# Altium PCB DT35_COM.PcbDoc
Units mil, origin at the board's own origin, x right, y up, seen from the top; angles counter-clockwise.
Board outline 1965 x 1965 mil, 2 copper layers (Top Layer, Bottom Layer); 79 components, 63 nets, 257 pads, 96 vias.
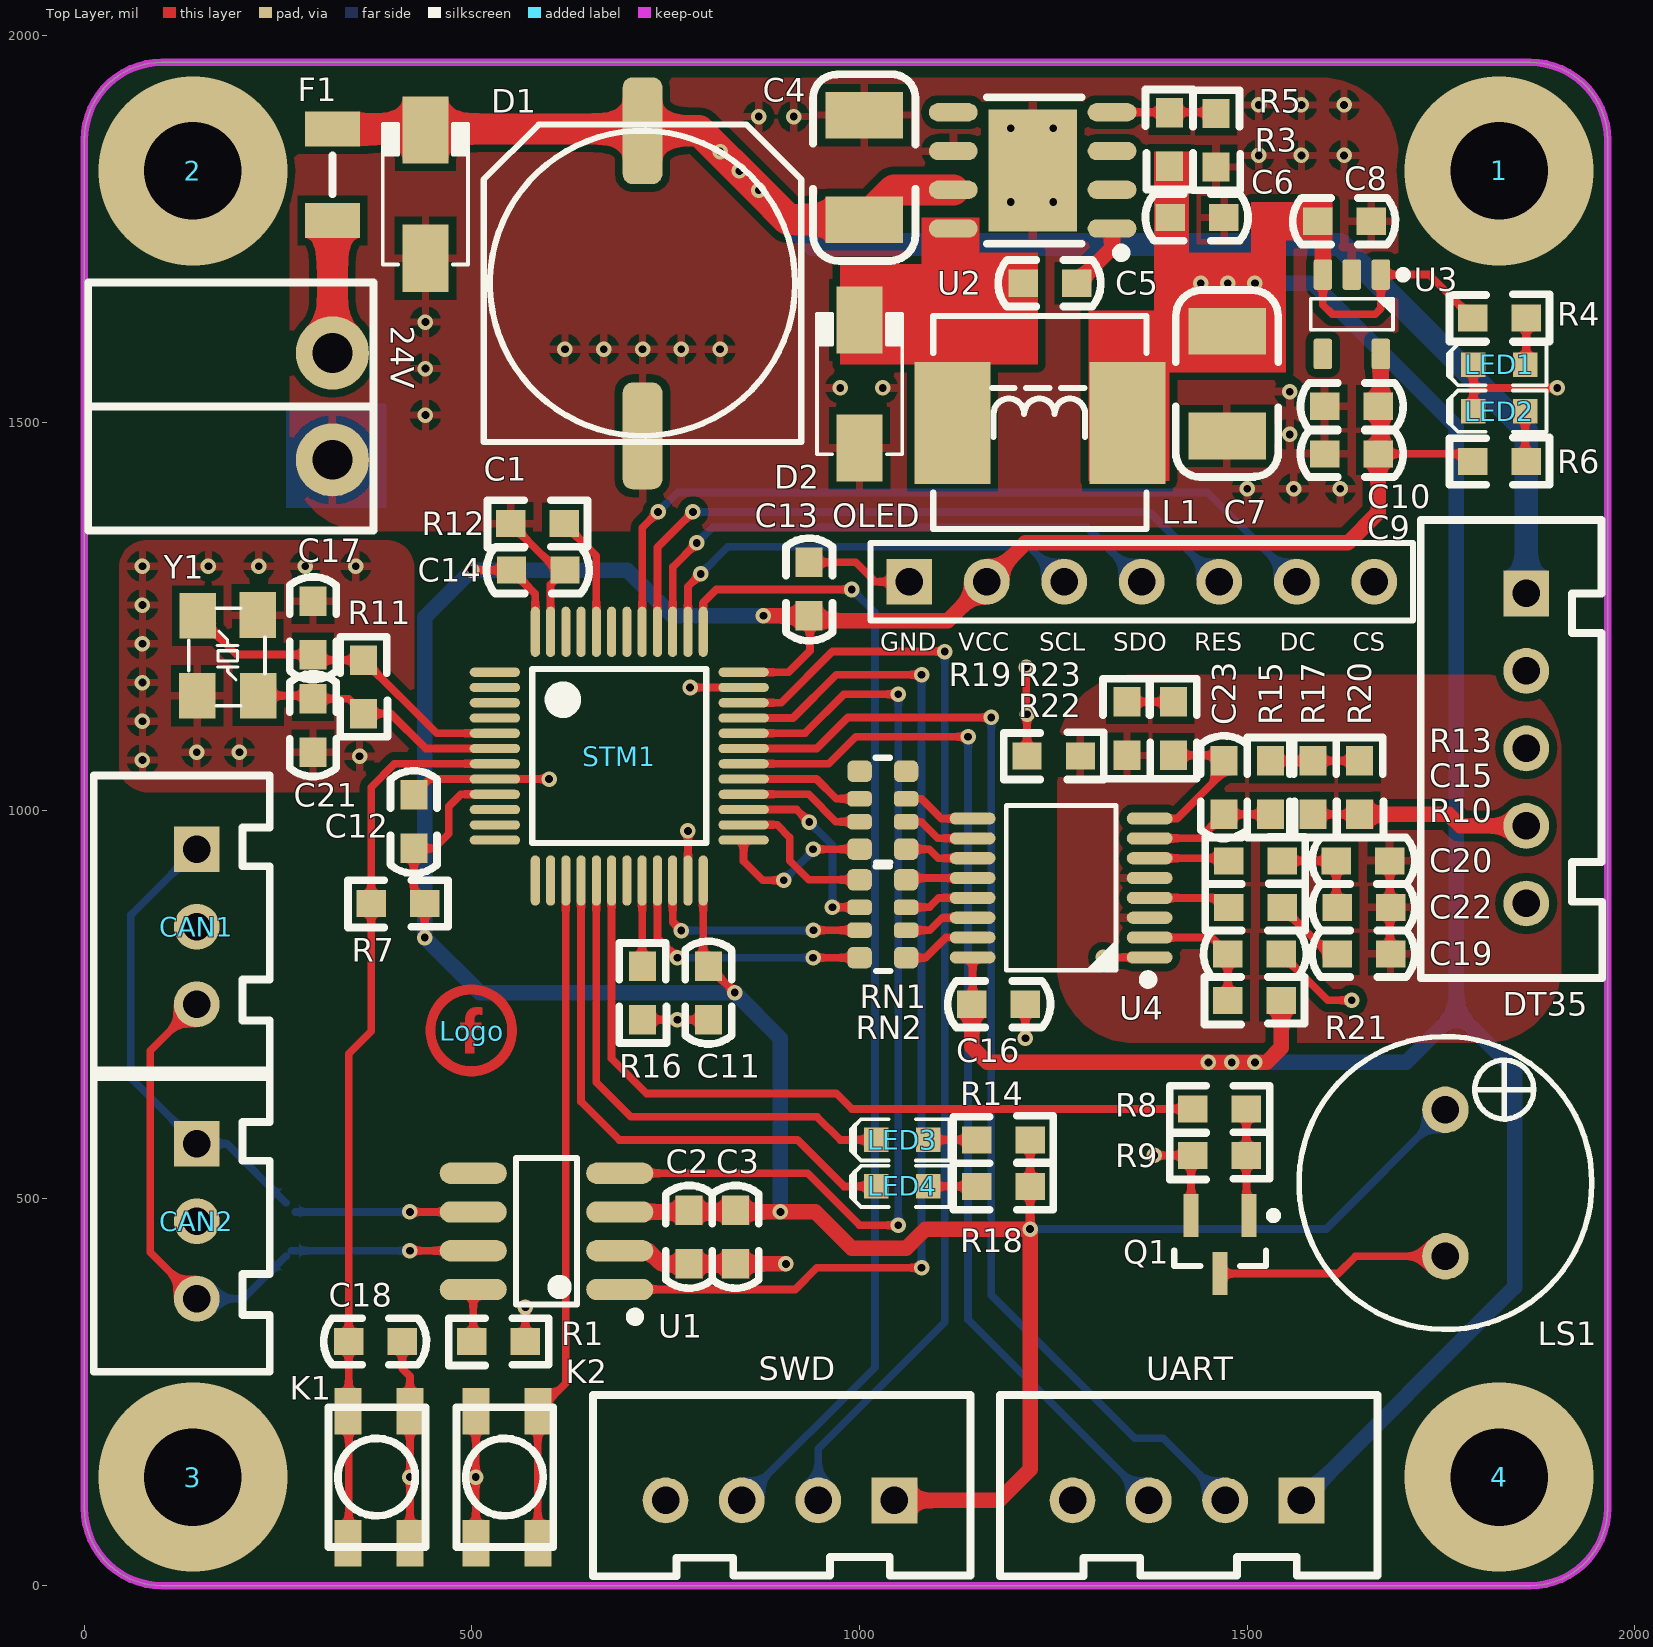
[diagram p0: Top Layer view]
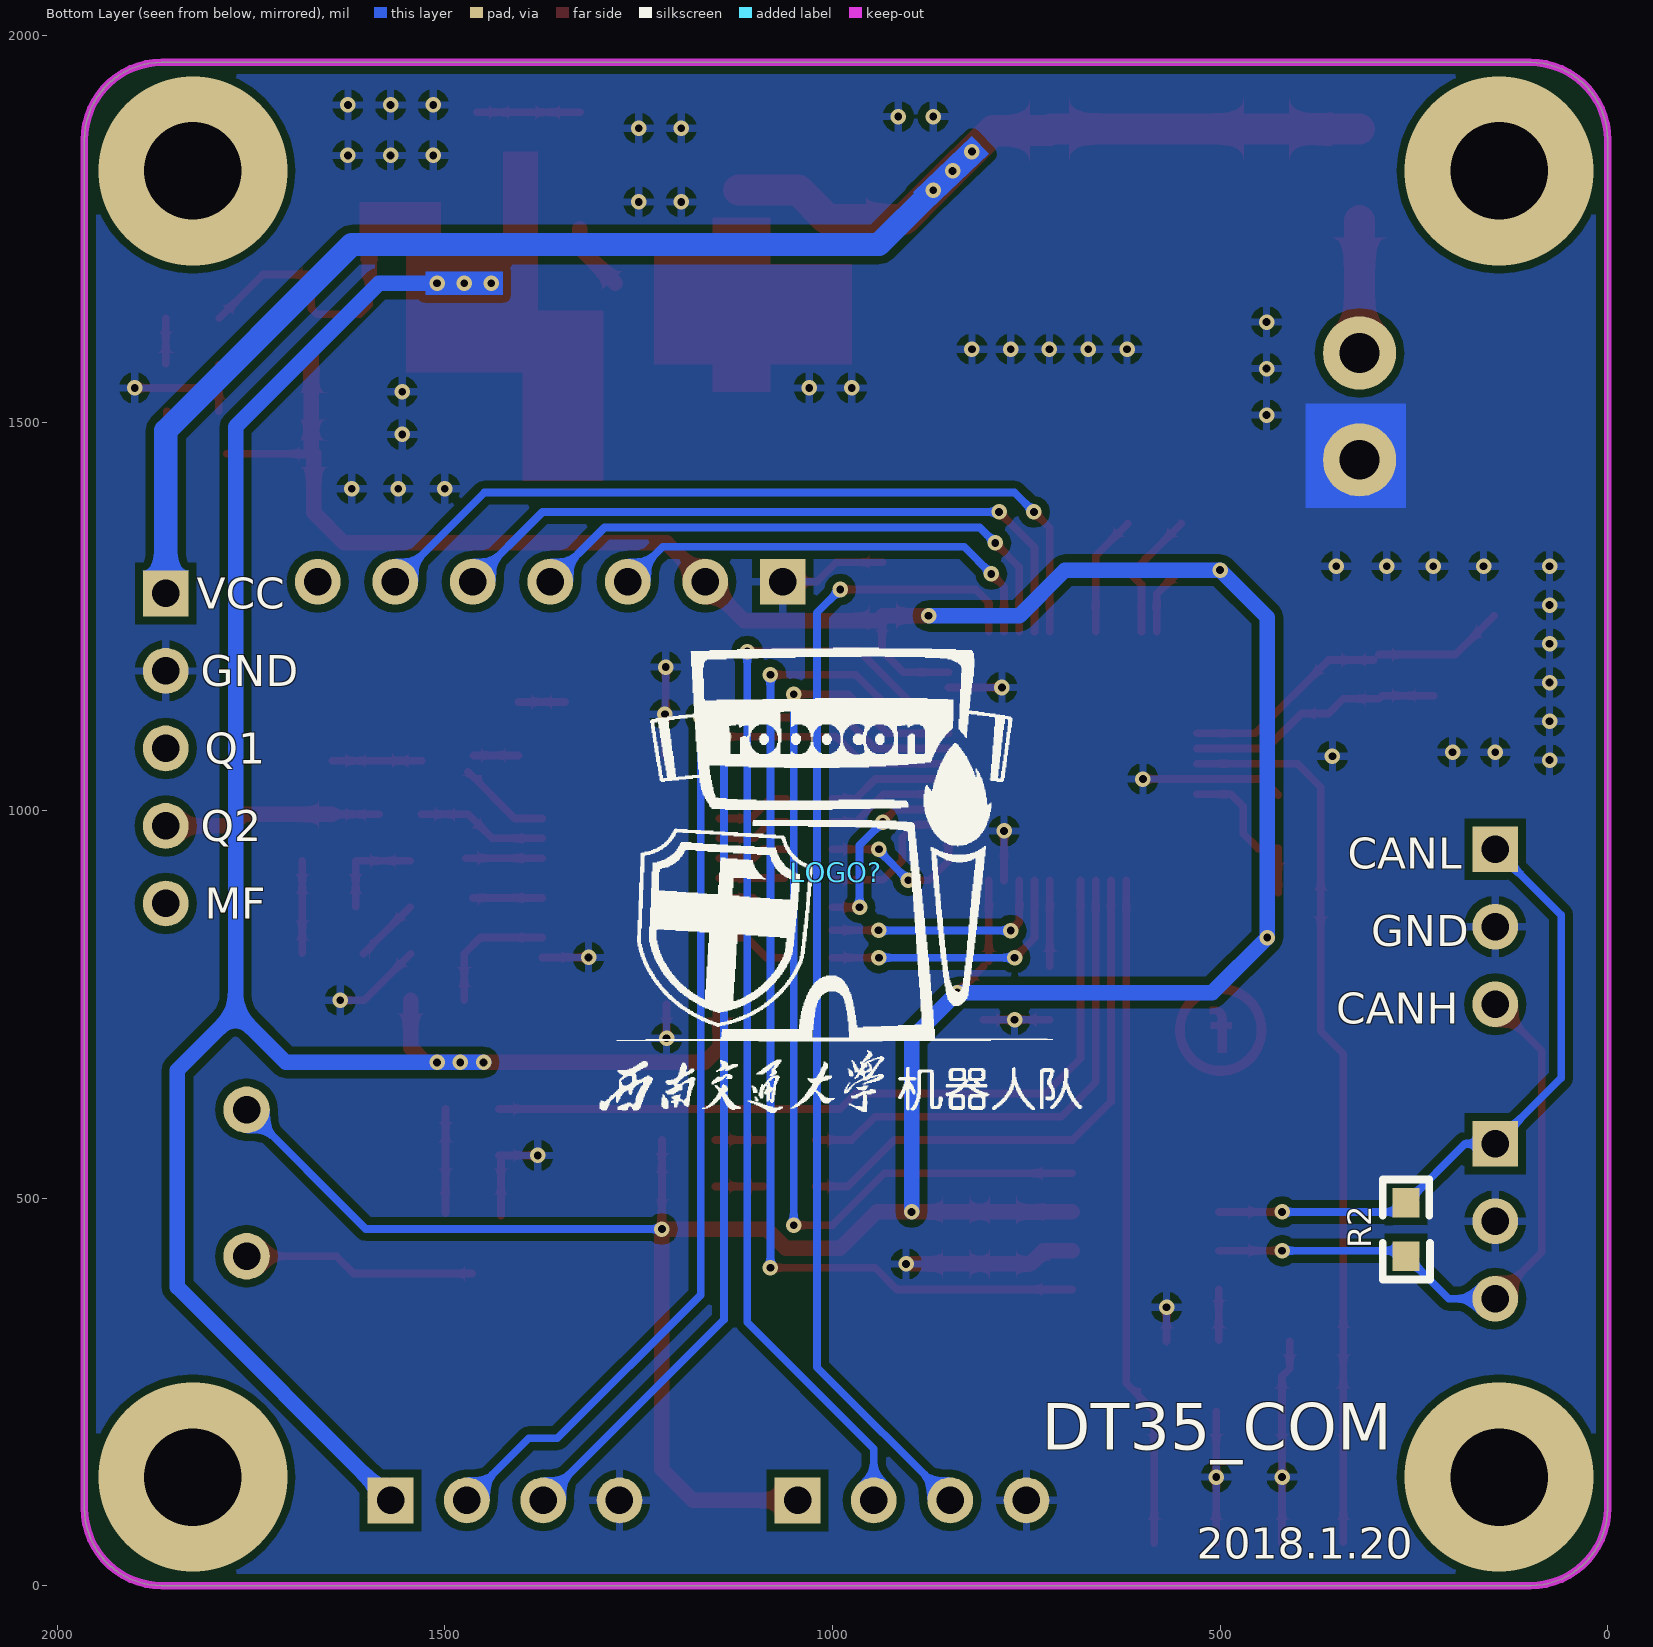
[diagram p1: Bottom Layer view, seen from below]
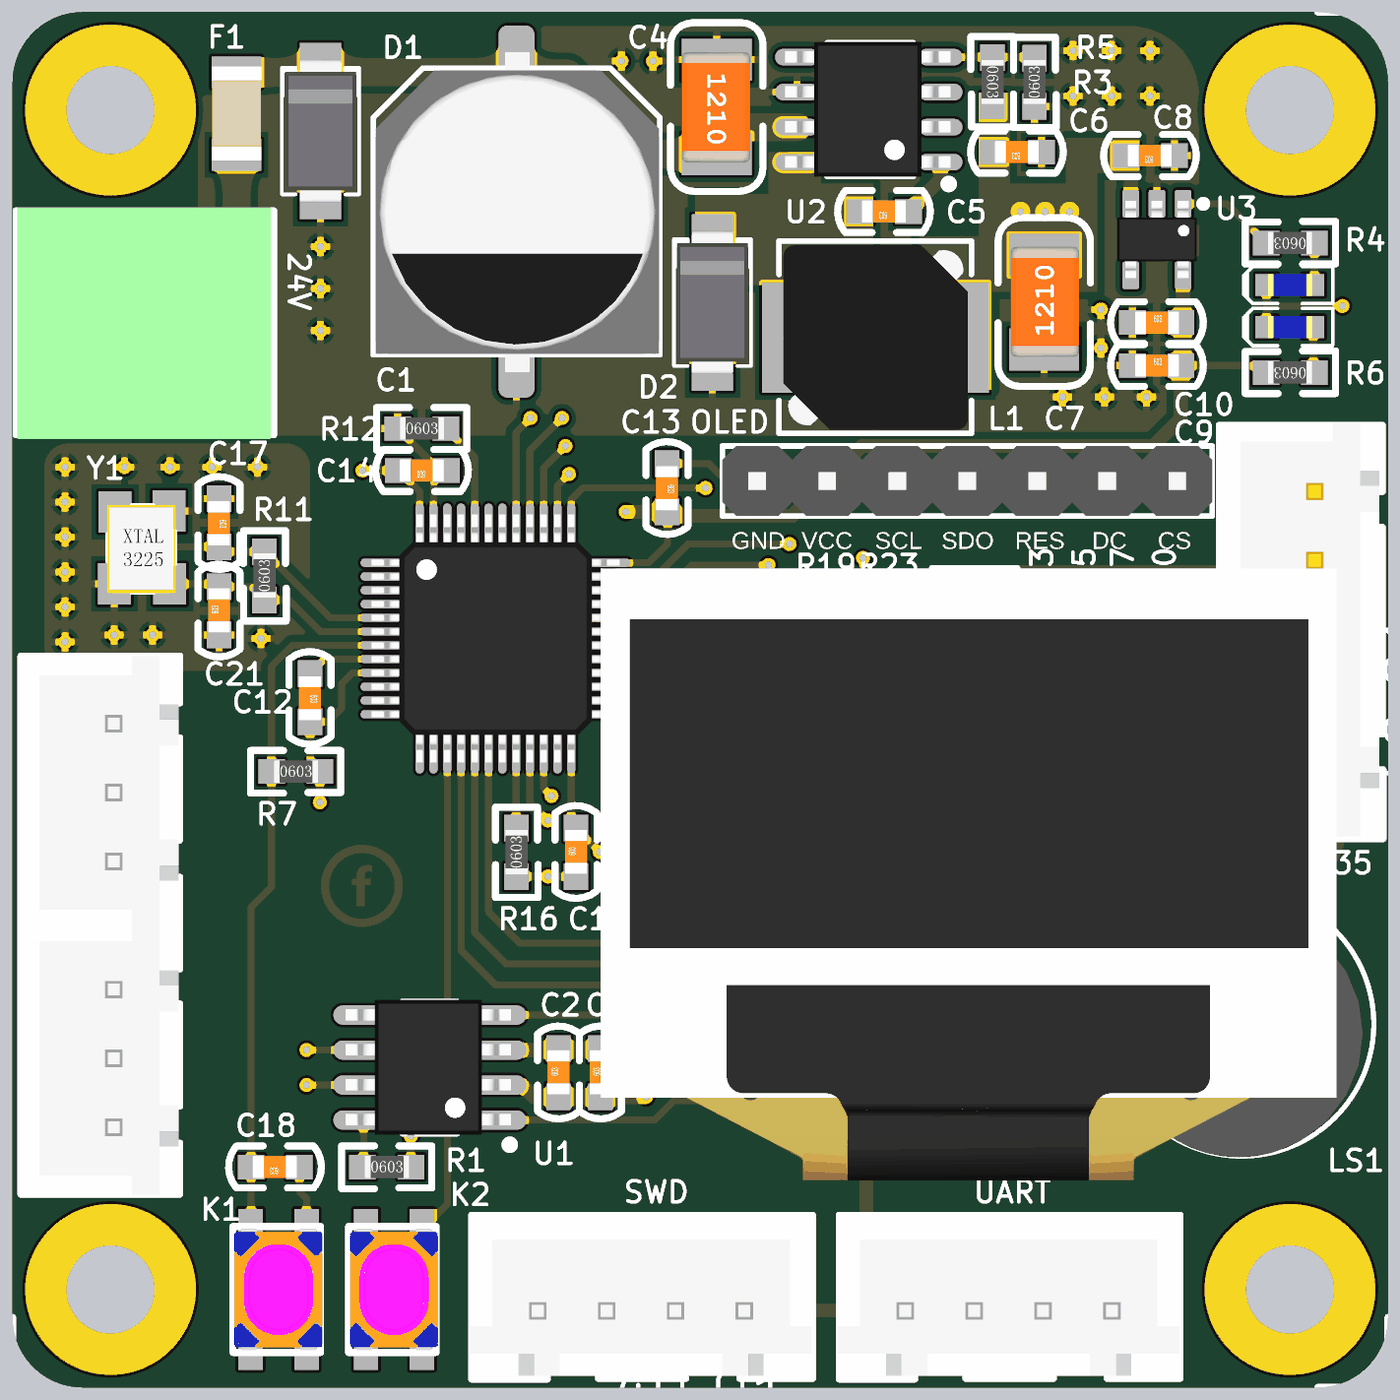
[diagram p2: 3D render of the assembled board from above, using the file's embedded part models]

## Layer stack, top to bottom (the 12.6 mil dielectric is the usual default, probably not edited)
Top Solder: solder mask 0.4, Solder Resist, Dk 3.5
Top Layer: signal copper 1.4
Dielectric 1: dielectric 12.6, FR-4, Dk 4.8
Bottom Layer: signal copper 1.4
Bottom Solder: solder mask 0.4, Solder Resist, Dk 3.5

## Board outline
100,0 cw(c100,100) 0,100 0,1865 cw(c100,1865) 100,1965 1865,1965 cw(c1865,1865) 1965,1865 1965,100 cw(c1865,100) 1865,0

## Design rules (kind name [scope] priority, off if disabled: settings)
Clearance [All] p1: gap=6 except(10: Arc-Poly Track-Poly SMDPad-Poly THPad-Poly Via-Poly Fill-Poly Poly-Poly Poly-Region Poly-Text)
HoleSize [All] p1: absolutevalues=TRUE maxlimit=1000 minlimit=1 maxpercent=80.000 minpercent=20.000
MinimumSolderMaskSliver [All] p1: minsoldermaskwidth=0
PolygonConnect [All] p1: connectstyle=Relief reliefconductorwidth=10 reliefentries=4 polygonreliefangle="90 Angle" airgapwidth=10
RoutingVias [All] p1: holewidth=28 width=50 viastyle="Through Hole" minholewidth=10 minwidth=20 maxholewidth=100 maxwidth=100
SilkToSilkClearance [All] p1: silktosilkclearance=0
SilkToSolderMaskClearance [IsPad] p1: minsilkscreentomaskgap=0 clearancetoexposedcopper=TRUE
SolderMaskExpansion [All] p1: expansion=4
Width [All] p1: maxlimit=1000 minlimit=10 preferedwidth=10
26 further rules are at their usual default settings.

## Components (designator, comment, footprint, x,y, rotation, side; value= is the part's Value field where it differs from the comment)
1 "Hole" HOLE2 1825,1825 r90 top
2 "Hole" HOLE2 140,1825 r90 top
3 "Hole" HOLE2 140,140 r90 top
4 "Hole" HOLE2 1825,140 r90 top
24V "Power" MEM030-350-2P 320,1590 r90 top
C1 "Cap_ELEC" C10X10 720,1680 r270 top
C2 "Cap" C0603 780,415 r90 top
C3 "Cap" C0603 840,415 r90 top
C4 "Cap" C1210 1000,1835 r270 top
C5 "Cap" C0603 1280,1680 r180 top
C6 "Cap" C0603 1470,1765 r180 top
C7 "Cap" C1210 1480,1545 r90 top
C8 "Cap" C0603 1660,1760 r180 top
C9 "Cap" C0603 1600,1460 r0 top
C10 "Cap" C0603 1600,1521.35 r0 top
C11 "Cap" C0603 805,730 r90 top
C12 "Cap" C0603 425,1020 r270 top
C13 "Cap" C0603 935,1320 r270 top
C14 "Cap" C0603 620,1310 r180 top
C15 "Cap" C0603 1475,815 r0 top
C16 "Cap" C0603 1145,750 r0 top
C17 "Cap" C0603 295,1270 r270 top
C18 "Cap" C0603 410,315 r180 top
C19 "Cap" C0603 1685,815 r180 top
C20 "Cap" C0603 1615,935 r0 top
C21 "Cap" C0603 295,1075 r90 top
C22 "Cap" C0603 1685,875 r180 top
C23 "Cap" C0603 1470,995 r90 top
CAN1 "Header 3" XH2.54-3 145,950 r270 top
CAN2 "Header 3" XH2.54-3 145,570 r270 top
D1 "Diode" DO-214AC 440,1795 r90 top
D2 "Diode" DO-214AC 1000,1550 r90 top
DT35 "Header 5" XH2.54-5 1860,1280 r270 top
F1 "Fuse" FUSE_1206 320,1820 r90 top
K1 "SW-PB" SW_4.2x3.2 340,55 r90 top
K2 "SW-PB" SW_4.2x3.2 505,55 r90 top
L1 "100uH" L-SMD-7X7 1120,1500 r0 top
LED1 "LED" LED_0603_BLUE 1825,1575 r180 top
LED2 "LED" LED_0603_BLUE 1825,1515 r180 top
LED3 "LED" LED_0603_BLUE 1055,575 r180 top
LED4 "LED" LED_0603_BLUE 1055,515 r180 top
Logo "Logo" Logo_f_3mm 500,715 r0 top
LOGO? "Robocon" SWJTURobocon_2*2cm 995,920 r180 bottom
LS1 "Buzzer" BUZZER_4.8MM 1755,520 r270 top
OLED "OLED" OLED_0.96_SPI 815,295 r0 top
Q1 "BJT_NPN" SOT23 1465,440 r270 top
R1 "Res" R0603 500,315 r0 top
R2 "Res" R0603 260,425 r90 bottom
R3 "Res" R0603 1400,1900 r270 top
R4 "Res" R0603 1860,1635 r180 top
R5 "Res" R0603 1460,1830 r90 top
R6 "Res" R0603 1860,1450 r180 top
R7 "Res" R0603 370,880 r0 top
R8 "Res" R0603 1430,615 r0 top
R9 "Res" R0603 1430,555 r0 top
R10 "Res" R0603 1545,875 r180 top
R11 "Res" R0603 360,1125 r90 top
R12 "Res" R0603 550,1370 r0 top
R13 "Res" R0603 1545,935 r180 top
R14 "Res" R0603 1220,575 r180 top
R15 "Res" R0603 1530,995 r90 top
R16 "Res" R0603 720,730 r90 top
R17 "Res" R0603 1585,995 r90 top
R18 "Res" R0603 1220,515 r180 top
R19 "Res" R0603 1405,1140 r270 top
R20 "Res" R0603 1645,995 r90 top
R21 "Res" R0603 1475,755 r0 top
R22 "Res" R0603 1285,1070 r180 top
R23 "Res" R0603 1345,1140 r270 top
RN1 "?K" RES-Pack-1*4-0603 1060,810 r180 top
RN2 "?K" RES-Pack-1*4-0603 1060,950 r180 top
STM1 "STM32F103C" STM32F_48 690,1070 r0 top
SWD "J-Link" "4PIN-2.54 A" 1045,110 r180 top
U1 "VP230" SOIC-8-150mil 595,455 r180 top
U2 "TPS5430" TPS5430 1220,1825 r180 top
U3 "XC6219" SOT23-5 1635,1640 r270 top
U4 "ADS868x" TSSOP_16 1260,900 r180 top
UART "UART" "4PIN-2.54 A" 1570,110 r180 top
Y1 "XTAL" XTAL-3225 185,1200 r0 top

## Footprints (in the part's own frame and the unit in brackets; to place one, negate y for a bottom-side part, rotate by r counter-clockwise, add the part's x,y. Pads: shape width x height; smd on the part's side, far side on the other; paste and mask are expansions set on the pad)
"4PIN-2.54 A" [mm]
  rect 1.5x1.5 hole 0.9: 1(0,0)
  round 1.5 hole 0.9: 2(2.5,0) 3(5,0) 4(7.5,0)
  silkscreen extent -2.49,-3.45 9.88,2.49, body extent -2.47,-3.38 9.93,2.37, height 7
BUZZER_4.8MM [mil]
  round 60 hole 35.43: 1(-93.86,0.75) 2(95.12,0.75)
  silkscreen extent -188,-188 190,190, body extent -163,-180 191,174, height 177
C10X10 [mm]
  rrect50% 3.5x1.3 smd: 1(-5,0) 2(5,0)
  silkscreen extent -5.2,-5.2 5.2,5.2, body extent -5.77,-5.12 5.83,5.18, height 10.21
C0603 [mil]
  rect 38x35 smd: 1(0,0) 2(69,0)
  silkscreen extent -31,-30 101,30, body extent 4,-16 67,16, height 12
C1210 [mil]
  rect 60x100 smd: 1(-62,6) 2(73,6)
  silkscreen extent -115,-60 126,72, body extent -73,-44 85,54, height 67
DO-214AC [mm] "JEDEC DO214 variation AC. SMA"
  rect 2.2x1.5 smd: 1(-2.1,0) 2(2.1,0)
  silkscreen extent -2.3,-1.4 2.3,1.4, body extent -2.6,-1.3 2.6,1.3, height 2.42
FUSE_1206 [mm] "Chip Capacitor, Body 3.2x1.6mm, 1206, IPC Medium Density"
  rect 1.15x1.8 smd: 1(-1.5,0) 2(1.5,0)
  silkscreen extent -0.64,0 0.64,0, body extent -1.7,-0.9 1.7,0.9, height 1.74
HOLE2 [mil]
L-SMD-7X7 [mm] "7X7mm的贴片电感"
  rect 2.5x4 smd: 1(0,0) 2(5.73,0)
  silkscreen extent -0.64,-3.48 6.35,3.51, body extent -0.48,-3.35 6.22,3.35, height 2.9
LED_0603_BLUE [mm] "Chip Capacitor, 2-Leads, Body 1.6x0.8mm, IPC Medium Density"
  rect 0.8x0.8 smd: 1(-0.85,0) 2(0.85,0)
  Top Layer pour cut-out: -0.5,0.5 0.5,0.5 0.5,-0.5 -0.5,-0.5
  silkscreen extent -1.55,-0.67 1.68,0.67, body extent -0.8,-0.4 0.8,0.4, height 0.75
Logo_f_3mm [mil]
  Top Layer drawing of 1039 lines, arcs and shapes, not listed
MEM030-350-2P [mm]
  round 2.4 hole 1.3: 1(0,0) 2(-3.5,0)
  silkscreen extent -5.81,-1.35 2.31,8, body extent -5.96,-1.25 2.44,7.95, height 7.25
OLED_0.96_SPI [mm] "0.96寸OLED SPI"
  rect 1.5x1.5 hole 0.9: 1(6.325,25.4)
  round 1.5 hole 0.9: 2(8.865,25.4) 3(11.405,25.4) 4(13.945,25.4) 5(16.485,25.4) 6(19.025,25.4) 7(21.565,25.4)
  silkscreen extent 5.05,24.13 22.83,26.67, body extent 0,0 27.94,27.3, height 8.54
R0603 [mil] "1/10W"
  rect 38x35 smd: 1(0,0) 2(69,0)
  silkscreen extent -30,-31 99,30, body extent 4,-16 66,16, height 18
RES-Pack-1*4-0603 [mm] "4排阻,0603封装"
  rrect50% 0.8x0.7 smd: 1(0,0) 4(0,-2.554) 5(1.522,-2.554) 8(1.522,0)
  rrect50% 0.8x0.5 smd: 2(0,-0.902) 3(0,-1.652) 6(1.522,-1.652) 7(1.522,-0.902)
  silkscreen extent 0.51,-3 1,0.43, body extent 0,-3 1.52,0.43, height 0.38
SOIC-8-150mil [mm]
  oval 2.2x0.7 smd: 1(-2.429,1.853) 2(-2.429,0.583) 3(-2.429,-0.687) 4(-2.429,-1.957) 5(2.371,-1.957) 6(2.371,-0.687) 7(2.371,0.583) 8(2.371,1.853)
  silkscreen extent -3.08,-2.45 0.97,2.9, body extent -2.98,-2.51 3.02,2.39, height 1.75
SOT23 [mm] "SOT23, 3-Leads, Body 3.0x2.5mm (max), Pitch 0.95mm, IPC Medium Density"
  rect 1.4x0.5 smd: 1(-0.95,0.95) 2(-0.95,-0.95) 3(0.95,0)
  silkscreen extent -1.07,-1.5 0.7,1.88, body extent -1.4,-1.45 1.4,1.45, height 1.29
SOT23-5 [mm]
  round 0.5 on Mech14: 0(0,0)
  rrect25% 1x0.6 smd: 1(-1.3,0.95) 2(-1.3,0) 3(-1.3,-0.95) 4(1.3,-0.95) 5(1.3,0.95)
  silkscreen extent -1.42,-1.35 0.51,1.81, body extent -1.4,-1.45 1.4,1.45, height 1.44
STM32F_48 [mm] "TSQFP, 48-Leads, Body 9.0x9.0mm (max), Pitch 0.50mm, IPC Medium Density"
  oval 1.65x0.3 smd: 1(-4.075,2.75) 2(-4.075,2.25) 3(-4.075,1.75) 4(-4.075,1.25) 5(-4.075,0.75) 6(-4.075,0.25) 7(-4.075,-0.25) 8(-4.075,-0.75) 9(-4.075,-1.25) 10(-4.075,-1.75) 11(-4.075,-2.25) 12(-4.075,-2.75) 25(4.075,-2.75) 26(4.075,-2.25) 27(4.075,-1.75) 28(4.075,-1.25) 29(4.075,-0.75) 30(4.075,-0.25) 31(4.075,0.25) 32(4.075,0.75) 33(4.075,1.25) 34(4.075,1.75) 35(4.075,2.25) 36(4.075,2.75)
  oval 0.3x1.65 smd: 13(-2.75,-4.075) 14(-2.25,-4.075) 15(-1.75,-4.075) 16(-1.25,-4.075) 17(-0.75,-4.075) 18(-0.25,-4.075) 19(0.25,-4.075) 20(0.75,-4.075) 21(1.25,-4.075) 22(1.75,-4.075) 23(2.25,-4.075) 24(2.75,-4.075) 37(2.75,4.075) 38(2.25,4.075) 39(1.75,4.075) 40(1.25,4.075) 41(0.75,4.075) 42(0.25,4.075) 43(-0.25,4.075) 44(-0.75,4.075) 45(-1.25,4.075) 46(-1.75,4.075) 47(-2.25,4.075) 48(-2.75,4.075)
  silkscreen extent -2.85,-2.85 2.85,2.85, body extent -4.5,-4.5 4.5,4.5, height 1.59
SW_4.2x3.2 [mil]
  rect 60x35 smd: 1(0,0) 1(170,0) 2(0,-80) 2(170,-80)
  silkscreen extent -5,-100 175,25, body extent -6,-103 176,23, height 98
SWJTURobocon_2*2cm [mil]
  silkscreen extent -305,-310 317,289
TPS5430 [mm]
  oval 1.6x0.6 smd: 1(-2.684,1.889) 2(-2.684,0.619) 3(-2.684,-0.651) 4(-2.684,-1.921) 5(2.516,-1.921) 6(2.516,-0.651) 7(2.516,0.619) 8(2.516,1.889)
  rect 2.9x4 smd: 9(-0.084,-0.016)
  silkscreen extent -3.13,-2.42 1.42,2.83, body extent -3.05,-2.48 2.95,2.42, height 1.75
TSSOP_16 [mm] "TSSOP, 16 Leads, Body 5.1x4.5mm (max), Pitch 0.65mm, IPC Medium Density"
  round 0.508 on Mech14: 0(0,0)
  oval 1.5x0.4 smd paste-0.051: 1(-2.9,2.275) 2(-2.9,1.625) 3(-2.9,0.975) 4(-2.9,0.325) 5(-2.9,-0.325) 6(-2.9,-0.975) 7(-2.9,-1.625) 8(-2.9,-2.275) 9(2.9,-2.275) 10(2.9,-1.625) 11(2.9,-0.975) 12(2.9,-0.325) 13(2.9,0.325) 14(2.9,0.975) 15(2.9,1.625) 16(2.9,2.275)
  silkscreen extent -3,-2.7 1.8,3.15, body extent -3.25,-2.55 3.25,2.55, height 1.2
XH2.54-3 [mm]
  rect 1.5x1.5 hole 0.9: 1(0,0)
  round 1.5 hole 0.9: 2(2.54,0) 3(5.08,0)
  silkscreen extent -2.41,-3.38 7.47,2.39, body extent -2.41,-3.41 7.49,2.34, height 7
XH2.54-5 [mm]
  rect 1.5x1.5 hole 0.9: 1(0,0)
  round 1.5 hole 0.9: 2(2.54,0) 3(5.08,0) 4(7.62,0) 5(10.16,0)
  silkscreen extent -2.4,-3.45 12.6,2.49, body extent -2.51,-3.39 12.52,2.36, height 7
XTAL-3225 [mil]
  rect 47.24x59.06 smd: 1(-38.5,51) 2(-39.5,-52) 3(39.5,-52) 4(38.5,52)
  silkscreen extent -50,-65 48,61, body extent -50,-65 48,61, height 31

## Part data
1 2 3 4: "定位孔"
24V: library part Power_24V, "24V电源"
C1 C2 C3 C4 C5 C6 C7 C8 C9 C10 C11 C12 C13 C14 C15 C16 C17 C18 C19 C20 C21 C22 C23: "Capacitor"
CAN1 CAN2: "Header, 3-Pin"
DT35: "Header, 5-Pin"
K1 K2: "轻触开关"
L1: library part Lnd, "电感"
LOGO?: library part LOGO_Robocon, "队徽"
OLED: "12864_0.96'OLED"
Q1: "Transistor"
R1 R2 R3 R4 R5 R6 R7 R8 R9 R10 R11 R12 R13 R14 R15 R16 R17 R18 R19 R20 R21 R22 R23: "Resistor"
RN1 RN2: library part RES-Pack-1*4-8x, "4排阻"
STM1: "MCU"
SWD: library part Comm_SWD, "调试接口_SWD"
U1: "CAN总线收发器"
U2: "Power"
U3: "LDO"
U4: "ADC"
UART: library part Comm_UART, "UART通信接口"
Y1: library part XTAL_4, "Crystal Oscillator"

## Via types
v1: diameter 20, hole 10, Top Layer to Bottom Layer, 92 vias
v2: diameter 244.09, hole 125.98, Top Layer to Bottom Layer, 4 vias

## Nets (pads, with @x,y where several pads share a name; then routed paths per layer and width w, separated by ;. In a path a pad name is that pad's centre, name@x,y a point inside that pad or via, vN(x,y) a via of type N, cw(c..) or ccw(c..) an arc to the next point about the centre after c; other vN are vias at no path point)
3V3: C2.2 C3.2 C9.2 C10.2 C11.2 C12.2 C13.2 C14.2 LS1.1 OLED.2 R6.2 R7.2 R14.1 R18.1 STM1.9 STM1.24 STM1.36 STM1.48 SWD.1 U1.3 U3.5 | length 5269.5
  Top Layer w10: R7.2@425,894 C12.2 451,951 470,970 470,1005 485.79,1020.79 STM1.9 ; v1(439,836) R7.2 ; v1(500,1310) C14.2 581.73,1279.27 STM1.48 ; C11.2@798.27,805.73 STM1.24 ; C11.2 v1(839,765) ; STM1.36 908.27,1178.27 936,1206 C13.2@936,1250 ; v1(1220,460) R18.1 R14.1 ; C9.2 R6.2@1781,1460
  Top Layer w20: U1.3 v1(897.95,482.05) 942.95,482.05 990,435 1060,435 1085,460 v1(1220,460) 1220,150 1180,110 SWD.1 ; v1(876,1251) C13.2 941,1245 1114,1245 OLED.2 1214,1345 1630,1345 1669,1384 C9.2 ; C9.2@1672.4,1463.4 U3.5
  Bottom Layer w10: v1(1220,460) 1601.89,460 LS1.1
  Bottom Layer w20: v1(876,1251) 759,1251 700,1310 v1(500,1310) 439,1249 v1(439,836) 510,765 v1(839,765) 897.95,706.05 v1(897.95,482.05)
5V: C6.2 C7.2 C8.2 C16.1 L1.2 R3.2 R4.2 R21.2 U3.1 U3.3 U4.16 UART.1 | length 3173.9
  Top Layer w10: C16.1@1145.83,750.83 U4.16 ; U3.3 1597.6,1652.4 1610,1640 1665,1640 1672.4,1647.4 U3.1 1734.82,1691.18 R4.2
  Top Layer w20: C16.1 1145,695 1165,675 v1(1510,675) 1525,675 1544,694 R21.2 ; U3.3 C8.2@1597.6,1753.4
  Bottom Layer w20: v1(1450,675) 1705,675 1770,740 ; v1(1510,1680) 1585,1680 1770,1495 1770,740 ; UART.1 1845,385 1845,665 1770,740
  other v1: 1480,675 1440,1680 1475,1680
AD: C23.1 R15.1 U4.7 | length 168.7
  Top Layer w10: U4.7 1438.98,963.98 C23.1 R15.1
AGND: C19.1 C20.2 C22.1 R22.1 R23.2 U4.3 U4.5 | length 119
  Top Layer w10: C19.1@1684,816 C20.2
ALARM: RN1.7 STM1.22 | length 294.7
  Top Layer w10: STM1.22 758.9,856.1 v1(770,845) ; v1(940.5,845.5) RN1.7
  Bottom Layer w10: v1(770,845) v1@935.99,845
AVDD: C15.1 R21.1 U4.2 | length 169.5
  Top Layer w10: U4.2 1453.98,836.02 C15.1 R21.1
BOOT0: R12.2 STM1.44 | length 156.7
  Top Layer w10: R12.2 660.47,1328.53 STM1.44
BOOT1: R16.2 STM1.20 | length 110.1
  Top Layer w10: R16.2@719.53,799.47 STM1.20
BUZZER: R8.1 STM1.18 | length 1006.4
  Top Layer w10: STM1.18 680.16,679.84 725,635 970,635 990,615 R8.1
CAN_RX: STM1.32 U1.4 | length 1292.6
  Top Layer w10: U1.4 932.95,532.05 1000,465 v1(1050,465) ; STM1.32 929.53,1099.53 980,1150 v1(1050,1150)
  Bottom Layer w10: v1(1050,465) v1(1050,1150)
CAN_TX: STM1.33 U1.1 | length 1418.6
  Top Layer w10: U1.1 917.05,382.05 945,410 v1(1080,410) ; STM1.33 914.21,1119.21 970,1175 v1(1080,1175)
  Bottom Layer w10: v1(1080,410) v1(1080,1175)
CANH: CAN1.3 CAN2.3 R2.1 U1.7 | length 802.1
  Top Layer w10: CAN2.3 85,430 85,690 CAN1.3 ; v1(420,432.05) U1.7
  Bottom Layer w10: CAN2.3 205,370 R2.1 ; R2.1@267.05,432.05 v1(420,432.05)
CANL: CAN1.1 CAN2.1 R2.2 U1.6 | length 826.6
  Top Layer w10: v1(420,482.05) U1.6
  Bottom Layer w10: CAN1.1 60,865 60,655 CAN2.1 184,570 R2.2 ; R2.2@271.95,482.05 v1(420,482.05)
CLK: STM1.37 SWD.3 | length 1495.1
  Top Layer w10: STM1.37 798.27,1268.27 815,1285 v1(990,1285)
  Bottom Layer w10: SWD.3 1020,281.85 1020,1255 v1(990,1285)
CONVST: RN2.8 STM1.25 | length 204.8
  Top Layer w10: STM1.25 850.43,934.57 875,910 v1(902.17,910) ; v1(940,950) RN2.8
  Bottom Layer w10: v1@902.17,912.17 v1(902.17,910) v1@940,947.83
D0: OLED.3 STM1.38 | length 583.5
  Top Layer w10: STM1.38 778.58,1288.58 v1(795,1305)
  Bottom Layer w10: v1(795,1305) 830,1340 1219,1340 OLED.3
D1: OLED.4 STM1.39 | length 738.7
  Top Layer w10: STM1.39 758.9,1313.9 v1(790,1345)
  Bottom Layer w10: v1(790,1345) 810,1365 1294,1365 OLED.4
DC: OLED.6 STM1.41 | length 1045
  Top Layer w10: STM1.41 719.53,1364.53 v1(740,1385)
  Bottom Layer w10: v1(740,1385) 765,1410 1449,1410 OLED.6
DIO: STM1.34 SWD.2 | length 1449.6
  Top Layer w10: STM1.34 898.9,1138.9 965,1205 v1(1110,1205)
  Bottom Layer w10: SWD.2 946.57,176.57 1110,340 v1(1110,1205)
FB: R3.1 R5.2 U2.4 | length 132.7
  Top Layer w10: U2.4 R5.2@1458.37,1900.63
GND: 24V.2 C1.2 C2.1 C3.1 C4.1 C6.1 C7.1 C8.1 C9.1 C10.1 C11.1 C12.1 C13.1 C14.1 C15.2 C16.2 C17.1 C18.1 C21.1 CAN1.2 CAN2.2 D1.1 D2.1 DT35.2 K1.2 K2.1 LED1.2 LED2.2 OLED.1 Q1.2 R1.2 R5.1 R9.1 R12.1 R16.1 R22.2 STM1.8 STM1.23 STM1.35 STM1.47 SWD.4 U1.2 U2.6 U2.9 U3.2 U4.1 UART.4 Y1.2 Y1.4 | length 2050.6
  Top Layer w10: C18.1 410,280 420,270 K1.2@420,55 ; C12.1 445.47,1040.47 STM1.8 v1(599.53,1040.47) ; K2.1@505,55 K2.1@505,225 ; R12.1 610,1310 C14.1 601.42,1291.42 STM1.47 ; R1.2 v1(569,359) ; R16.1 C11.1 ; STM1.23 v1(778.58,973.58) ; v1(781.42,1158.58) STM1.35 ; C13.1 995,1320 1020,1295 OLED.1 ; v1(1214,706) C16.2 ; v1(1215,1185) 1215,1125 v1(1216,1124) R22.2 ; v1(1314.57,810.43) U4.1 ; v1(1380,555) R9.1 ; Q1.2 R9.1@1427.6,552.6 ; C15.2 1604,755 v1(1635,755) ; LED2.2 1791.54,1545 ; LED1.2 1791.54,1545 ; v1(1900,1545) 1791.54,1545
  Top Layer w20: U1.2 727.95,432.05 745,415 C2.1 C3.1 v1(905,415)
  other v1: 420,140 505,140 765,730 75,1065 355,1070 145,1075 200,1075 75,1115 75,1165 75,1215 75,1265 75,1315 160,1315 225,1315 285,1315 350,1315 1500,1415 1560,1415 1620,1415 1555,1485 440,1510 1555,1540 975,1545 1030,1545 440,1570 620,1595 670,1595 720,1595 770,1595 820,1595 440,1630 1195,1785 1250,1785 1515,1845 1570,1845 1625,1845 1195,1880 1250,1880 870,1895 915,1895 1515,1910 1570,1910 1625,1910
KEY: K2.2 STM1.15 | length 869.5
  Top Layer w10: K2.2@585,55 585,225 621.1,261.1 STM1.15
LED0: LED3.2 STM1.17 | length 652
  Top Layer w10: STM1.17 660.47,649.53 705,605 945,605 975,575 LED3.2
LED1: LED4.2 STM1.16 | length 711.3
  Top Layer w10: STM1.16 640.79,624.21 690,575 920,575 980,515 LED4.2
MF: DT35.5
Net24V_1: 24V.1 F1.1 | length 170.9
  Top Layer w40: 24V.1 F1.1
NetC5_1: C5.1 U2.1 | length 89.5
  Top Layer w20: C5.1 1325.67,1725.67 U2.1
NetC5_2: C5.2 D2.2 L1.1 U2.8
NetC19_2: C19.2 R10.1 | length 84.9
  Top Layer w10: R10.1 C19.2@1605,815
NetC20_1: C20.1 C22.2 R13.1 | length 129
  Top Layer w10: R13.1 C20.1 C22.2@1615,876
NetC23_2: C23.2 R19.2 U4.8 | length 178.9
  Top Layer w10: U4.8 1409.57,989.57 C23.2@1470,1050 ; R19.2 C23.2@1463,1071
NetLED1_1: LED1.1 R4.1 | length 58.5
  Top Layer w10: LED1.1@1860,1576.54 R4.1
NetLED2_1: LED2.1 R6.1 | length 63.5
  Top Layer w10: R6.1@1858.46,1451.54 LED2.1
NetLED3_1: LED3.1 R14.2 | length 62.5
  Top Layer w10: LED3.1 R14.2
NetLED4_1: LED4.1 R18.2 | length 62.5
  Top Layer w10: LED4.1 R18.2
NetLS1_2: LS1.2 Q1.3 | length 300
  Top Layer w10: Q1.3 1617.6,402.6 1639.88,424.88 LS1.2
NetQ1_1: Q1.1 R8.2 R9.2 | length 134.2
  Top Layer w10: Q1.1@1499,480.8 R8.2
NetR1_1: R1.1 U1.8 | length 65.4
  Top Layer w10: R1.1@501.65,316.65 U1.8
NetR10_2: R10.2 U4.4 | length 89.6
  Top Layer w10: U4.4 R10.2@1463.8,887.2
NetR13_2: R13.2 U4.6 | length 98.4
  Top Layer w10: U4.6 R13.2@1472.61,938.39
NetR15_2: R15.2 R17.2 R20.2 | length 115
  Top Layer w10: R15.2 R17.2 R20.2
NetR19_1: R19.1 R23.1 | length 60
  Top Layer w10: R23.1 R19.1
NetRN1_1: RN1.1 U4.15 | length 96.6
  Top Layer w10: RN1.1 1085,810 1111.02,836.02 U4.15
NetRN1_2: RN1.2 U4.14 | length 92.5
  Top Layer w10: RN1.2 1090.5,845.5 1106.61,861.61 U4.14
NetRN1_3: RN1.3 U4.13 | length 90.9
  Top Layer w10: RN1.3 1090.05,875.05 1102.2,887.2 U4.13
NetRN1_4: RN1.4 U4.12 | length 83.6
  Top Layer w10: RN1.4@1062.24,912.8 U4.12
NetRN2_1: RN2.1 U4.11 | length 90.6
  Top Layer w10: RN2.1 1090,950 1101.61,938.39 U4.11
NetRN2_2: RN2.2 U4.10 | length 94.7
  Top Layer w10: RN2.2 1079.5,985.5 1101.02,963.98 U4.10
NetRN2_3: RN2.3 U4.9 | length 96.4
  Top Layer w10: RN2.3 1079.94,1015.06 1105.43,989.57 U4.9
OIN: C17.2 R11.2 STM1.5 Y1.1 | length 435.9
  Top Layer w10: Y1.1 196.5,1201 C17.2 ; C17.2@302,1194 R11.2 454.47,1099.53 STM1.5
OOUT: C21.2 R11.1 STM1.6 Y1.3 | length 327.6
  Top Layer w10: Y1.3 C21.2@291,1148 ; C21.2 341,1144 R11.1 395,1125 440.16,1079.84 STM1.6
Q1: DT35.3
Q2: DT35.4 R17.1 R20.1 | length 281.2
  Top Layer w10: R17.1 R20.1
  Top Layer w20: R20.1 1760,995 1775,980 DT35.4
RES: OLED.5 STM1.40 | length 889.8
  Top Layer w10: STM1.40 739.21,1339.21 v1(785,1385)
  Bottom Layer w10: v1(785,1385) 1374,1385 OLED.5
RST: C18.2 K1.1 R7.1 STM1.7 | length 1158.1
  Top Layer w10: K1.1@341,56 C18.2 341,686 370,715 R7.1 370,1030 400.16,1060.16 STM1.7
RST_ADC: RN2.6 STM1.29 | length 160.2
  Top Layer w10: STM1.29 944.53,1040.47 969.94,1015.06 RN2.6
RVS: RN1.8 STM1.21 | length 345.3
  Top Layer w10: STM1.21 739.21,835.79 v1(765,810) ; v1(940,810) RN1.8
  Bottom Layer w10: v1(765,810) v1(940,810)
RX: STM1.31 UART.2 | length 1492.5
  Top Layer w10: STM1.31 944.84,1079.84 985,1120 v1(1170,1120)
  Bottom Layer w10: v1(1170,1120) 1170,375 1355,190 1391.57,190 UART.2
SCLK: RN1.5 STM1.26 | length 196.6
  Top Layer w10: STM1.26 893.58,981.42 910,965 910,935 934.45,910.55 RN1.5
SDI: RN2.7 STM1.28 | length 164.3
  Top Layer w10: STM1.28 934.21,1020.79 969.5,985.5 RN2.7
SDO-0: RN1.6 STM1.27 | length 248.6
  Top Layer w10: STM1.27 918.9,1001.1 v1(935,985) ; v1(965.05,875.05) RN1.6
  Bottom Layer w10: v1(935,985) 965.05,954.95 v1(965.05,875.05)
TX: STM1.30 UART.3 | length 1385.6
  Top Layer w10: STM1.30 960.16,1060.16 995,1095 v1(1140,1095)
  Bottom Layer w10: v1(1140,1095) 1140,343.15 UART.3
VCC: C1.1 C4.2 D1.2 DT35.1 F1.2 U2.7 | length 2190.7
  Top Layer w40: F1.2 C1.1@717.8,1879.06 ; C1.1 793.15,1876.85 v1(870,1800) 908,1762 C4.2 1044.63,1800.63 U2.7
  Bottom Layer w30: v1(870,1800) 940,1730 1620,1730 1860,1490 DT35.1
  other v1: 845,1825 820,1850
pads on no net: OLED.7 RN2.4 RN2.5 STM1.1 STM1.2 STM1.3 STM1.4 STM1.10 STM1.11 STM1.12 STM1.13 STM1.14 STM1.19 STM1.42 STM1.43 STM1.45 STM1.46 U1.5 U2.2 U2.3 U2.5 U3.0 U3.4 U4.0
copper on no net:
  other v2: 140,140 1825,140 140,1825 1825,1825

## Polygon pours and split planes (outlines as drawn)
AGND on Top Layer "Top Layer-No Net" (solid, remove dead copper, pour order 0): 1255,1030 1255,800 ccw(c1355,800) 1355,700 1520,700 1805,700 ccw(c1805,800) 1905,800 1905,960 1905,1075 ccw(c1805,1075) 1805,1175 1555,1175 1355,1175 ccw(c1355,1075) 1255,1075 1255,1015
GND on Top Layer "Top Layer-No Net" (solid, remove dead copper, pour order 4): 265,1530 265,1845 cw(c365,1845) 365,1945 835,1945 1595,1945 cw(c1595,1845) 1695,1845 1695,1650 1695,1460 cw(c1595,1460) 1595,1360 1130,1360 365,1360 cw(c365,1460) 265,1460 265,1530
GND on Top Layer "Top Layer-No Net" (solid, remove dead copper, pour order 8): 45.24,1198.74 45.24,1313.74 cw(c80.24,1313.74) 80.24,1348.74 390.24,1348.74 cw(c390.24,1313.74) 425.24,1313.74 425.24,1053.74 cw(c395.24,1053.74) 395.24,1023.74 80.24,1023.74 cw(c80.24,1058.74) 45.24,1058.74
GND on Bottom Layer "Top Layer-No Net" (solid, remove dead copper, pour order 2): -105,1090 -105,1955 cw(c-5,1955) -5,2055 255,2055 1970,2055 cw(c1970,1955) 2070,1955 2070,1405 2070,50 cw(c1970,50) 1970,-50 1505,-50 -5,-50 cw(c-5,50) -105,50 -105,1015

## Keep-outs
Keep-Out Layer:
  lines w10: 0,100 ccw(c100,100) 100,0 335,0 1865,0 ccw(c1865,100) 1965,100 1965,480 1965,1865 ccw(c1865,1865) 1865,1965 100,1965 ccw(c100,1865) 0,1865 0,100

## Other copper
Top Layer:
  rectangle net NetC5_2: 1080,1540 1155,1765
  rectangle net NetC5_2: 1130,1575 1230,1720
  rectangle net NetC5_2: 975,1575 1125,1705
  rectangle net 5V: 1295,1425 1400,1645
  rectangle net 5V: 1400,1565 1550,1720
  rectangle net 5V: 1380,1630 1425,1850
  rectangle net 5V: 1505,1720 1550,1785
  rectangle net 5V: 1550,1735 1610,1785
Bottom Layer:
  region net VCC: 874.3,1774.3 896.29,1797.42 820,1870 798.01,1846.89
  region net 5V: 1525,1665 1525,1695 1425,1695 1425,1665
  rectangle net GND: 260,1390 390,1525

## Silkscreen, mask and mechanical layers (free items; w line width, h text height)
Bottom Overlay:
  text "VCC" at 1820,1260 h40
  text "GND" at 1815,1160 h40
  text "Q1" at 1810,1060 h40
  text "Q2" at 1815,960 h40
  text "CANL" at 335,925 h40
  text "MF" at 1810,860 h40
  text "GND" at 305,825 h40
  text "CANH" at 350,725 h40
  text "DT35_COM" at 730,175 h60
  text "2018.1.20" at 530,35 h40

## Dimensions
1865,1965 to 1865,0 on Top Overlay
0,100 to 1965,100 on Top Overlay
